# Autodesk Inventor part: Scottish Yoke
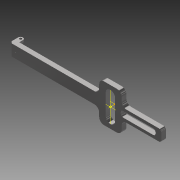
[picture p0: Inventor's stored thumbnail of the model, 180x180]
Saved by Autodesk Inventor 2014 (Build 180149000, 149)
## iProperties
Created: 2008-06
Part Number: Scottish Yoke
Document SubType Name: Modeling
Designer: tangg
Density: 7.84 g/cm^3
Mass: 21.4252 g
Surface Area: 112.705 cm^2
Volume: 21.4252 cm^3
Stock Number: Scottish Yoke
Material: Steel, High Strength Low Alloy
Appearance: Steel - Polished
Author: tangg
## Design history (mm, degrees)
sketch "Sketch1"
  geometry: L1 (195.262, 4.445)-(195.262, -4.445); L2 (-7.938, -7.62)-(-7.938, 7.62); L3 (111.919, 25.4)-(142.081, 25.4); L4 (142.081, -25.4)-(111.919, -25.4); L5 (127, 42.862)-(127, -39.687); L6 (127, 19.844)-(127, 19.844); L7 (133.35, 13.494)-(133.35, -13.494); L8 (127, -19.844)-(127, -19.844); L9 (120.65, -13.494)-(120.65, 13.494); L10 (-7.938, 7.62)-(111.919, 7.62); L11 (142.081, 7.62)-(192.088, 7.62); L12 (192.088, -7.62)-(142.081, -7.62); L13 (111.919, -7.62)-(-7.938, -7.62); L14 (111.919, -25.4)-(111.919, -7.62); L15 (111.919, 7.62)-(111.919, 25.4); L16 (142.081, 25.4)-(142.081, 7.62); L17 (142.081, -7.62)-(142.081, -25.4); C1 r 0.408 at (0, 0); A1 r 3.175 centre (192.088, 4.445) between (195.262, 4.445) and (192.088, 7.62); A2 r 3.175 centre (192.088, -4.445) between (192.088, -7.62) and (195.262, -4.445); A3 r 6.35 centre (127, 13.494) between (127, 19.844) and (120.65, 13.494); A4 r 6.35 centre (127, 13.494) between (133.35, 13.494) and (127, 19.844); A5 r 6.35 centre (127, -13.494) between (127, -19.844) and (133.35, -13.494); A6 r 6.35 centre (127, -13.494) between (120.65, -13.494) and (127, -19.844); 6 further points
  constraints: 34 end point, 14 tangent, 12 point on circle, 7 centre point, 4 equal radius, 4 midpoint, 3 horizontal alignment, 2 point on line, 1 coincident
  dimensions: "d0" = 15.24 distance of L2.start L2.end; "d1" = 203.2 distance between parallel lines of L1 L2; "d2" = 3.175 radius of A1; "d3" = 127 distance from line of L5 point (0, 0); "d4" = 6.35 radius of A3; "d43" = 25.4 distance from line of point (120.65, 0) L3; "d44" = 25.4 distance of point (111.919, 0) L4.end
extrude "Extrusion1" new body sketch "Sketch1" distance "d5" = 6.35; taper "d6" = 0 deg
workplane "Work Plane3"
workpoint "Work Point2"
  workaxis "Work Axis1"
workaxis "Work Axis2"
workaxis "Work Axis3"
fillet "Fillet1" dims "d20" = 6.35
sketch "Sketch10"
  geometry: L1 (144.049, 3.81)-(184.417, 3.81); L2 (187.592, 0.635)-(187.592, -0.635); L3 (184.417, -3.81)-(144.049, -3.81); L4 (140.874, -0.635)-(140.874, 0.635); L5 (135.731, -25.4)-(118.269, -25.4) reference; L6 (192.088, -7.62)-(148.431, -7.62) reference; L7 (195.262, 4.445)-(195.262, -4.445) reference; L8 (148.431, 7.62)-(192.088, 7.62) reference; L9 (118.269, 25.4)-(135.731, 25.4) reference; L10 (-7.938, 7.62)-(105.569, 7.62) reference; L11 (-7.938, -7.62)-(-7.938, 7.62) reference; L12 (105.569, -7.62)-(-7.938, -7.62) reference; L13 (133.35, 13.494)-(133.35, -13.494) reference; L14 (120.65, -13.494)-(120.65, 13.494) reference; L15 (-7.938, 7.62)-(82.337, 7.62); L16 (82.337, 7.62)-(89.968, 7.62); L17 (195.262, 4.445)-(195.262, -4.445) reference; L18 (-7.938, 0)-(195.263, 0); L19 (-7.938, -7.62)-(82.337, -7.62); L20 (82.337, -7.62)-(89.968, -7.62); L21 (142.081, -13.97)-(142.081, -19.05) reference; L22 (142.081, 19.05)-(142.081, 13.97) reference; L23 (111.919, 13.97)-(111.919, 19.05) reference; L24 (111.919, -19.05)-(111.919, -13.97) reference; C1 r 0.408 at (0, 0) reference; A1 r 6.35 centre (118.269, -19.05) between (111.919, -19.05) and (118.269, -25.4) reference; A2 r 6.35 centre (135.731, -19.05) between (135.731, -25.4) and (142.081, -19.05) reference; A3 r 6.35 centre (148.431, -13.97) between (148.431, -7.62) and (142.081, -13.97) reference; A4 r 3.175 centre (192.088, -4.445) between (192.088, -7.62) and (195.262, -4.445) reference; A5 r 3.175 centre (192.088, 4.445) between (195.262, 4.445) and (192.088, 7.62) reference; A6 r 6.35 centre (148.431, 13.97) between (142.081, 13.97) and (148.431, 7.62) reference; A7 r 6.35 centre (135.731, 19.05) between (142.081, 19.05) and (135.731, 25.4) reference; A8 r 6.35 centre (118.269, 19.05) between (118.269, 25.4) and (111.919, 19.05) reference; A9 r 6.35 centre (105.569, 13.97) between (105.569, 7.62) and (111.919, 13.97) reference; A10 r 6.35 centre (105.569, -13.97) between (111.919, -13.97) and (105.569, -7.62) reference; A11 r 6.35 centre (127, 13.494) between (133.35, 13.494) and (120.65, 13.494) reference; A12 r 6.35 centre (127, -13.494) between (120.65, -13.494) and (133.35, -13.494) reference; A13 r 3.175 centre (144.049, 0.635) between (144.049, 3.81) and (140.874, 0.635); A14 r 3.175 centre (144.049, -0.635) between (140.874, -0.635) and (144.049, -3.81); A15 r 3.175 centre (184.417, 0.635) between (187.592, 0.635) and (184.417, 3.81); A16 r 3.175 centre (184.417, -0.635) between (184.417, -3.81) and (187.592, -0.635); 3 further points
  constraints: 18 end point, 8 point on circle, 8 tangent, 4 centre point, 4 midpoint, 4 point on line, 2 equal radius, 2 horizontal alignment, 1 horizontal, 1 parallel
  dimensions: "d22" = 3.175 radius of A13; "d23" = 7.62 distance between parallel lines of L3 L1; "d24" = 3.175 radius of A15; "d25" = 7.62 distance from line of point (0, 0) L15; "d26" = 7.62 distance of L19.start L18.start
extrude "Extrusion7" cut sketch "Sketch10" stored distance "d27" = 19.05; taper "d28" = 0 deg
sketch "Sketch7"
  geometry: L1 (7.938, 0)-(7.938, -5); L2 (7.938, 0)-(-19.05, 0); L3 (-111.919, 0)-(7.938, 0) reference; L4 (7.938, 0)-(1.588, 0); L5 (1.588, 0)-(1.588, -5); L6 (7.938, -5)-(7.938, 0); L7 (1.588, -5)-(3.175, -5); L8 (6.35, -5)-(7.938, -5); L9 (7.938, 0)-(-111.919, 0) reference; A1 r 3.175 centre (4.763, -5) between (1.588, -5) and (7.938, -5); A2 r 1.587 centre (4.763, -5) between (3.175, -5) and (6.35, -5); 2 further points
  constraints: 14 end point, 4 point on circle, 2 centre point, 2 coincident, 2 collinear, 2 parallel, 1 point on line, 1 vertical
  dimensions: "d35" = 6.35 distance of L3.end L4.end; "d40" = 5 distance of L1.start L1.end; "d41" = 3.175 radius of A1; "d42" = 3.175 diameter of A2
extrude "Extrusion9" join sketch "Sketch7" stored distance "d36" = 15.24; taper "d37" = 0 deg
sketch "Sketch12"
  geometry: L1 (1.588, 0)-(7.938, 0); L2 (7.938, 6.35)-(7.938, -5) reference; L3 (1.588, -5)-(1.588, 0) reference; A1 r 3.175 centre (4.763, -5) between (1.588, -5) and (7.938, -5) reference; A2 r 3.175 centre (4.763, -5) between (1.588, -5) and (7.938, -5) reference; 1 further point
  constraints: 2 end point, 1 point on line
extrude "Extrusion11" cut sketch "Sketch12" stored distance "d45" = 7.62; taper "d46" = 0 deg
chamfer "Chamfer1" distance "d47" = 2.54; stored, may be unused: second distance "d48" = 3.175, angle "d49" = 45 deg
workpoint "Work Point4"
workaxis "Work Axis5"
body "Solid1"
node "Projected Loop6"
node "Projected Loop7"
other parameters: "d30" = 6.35, "d34" = 6.35
